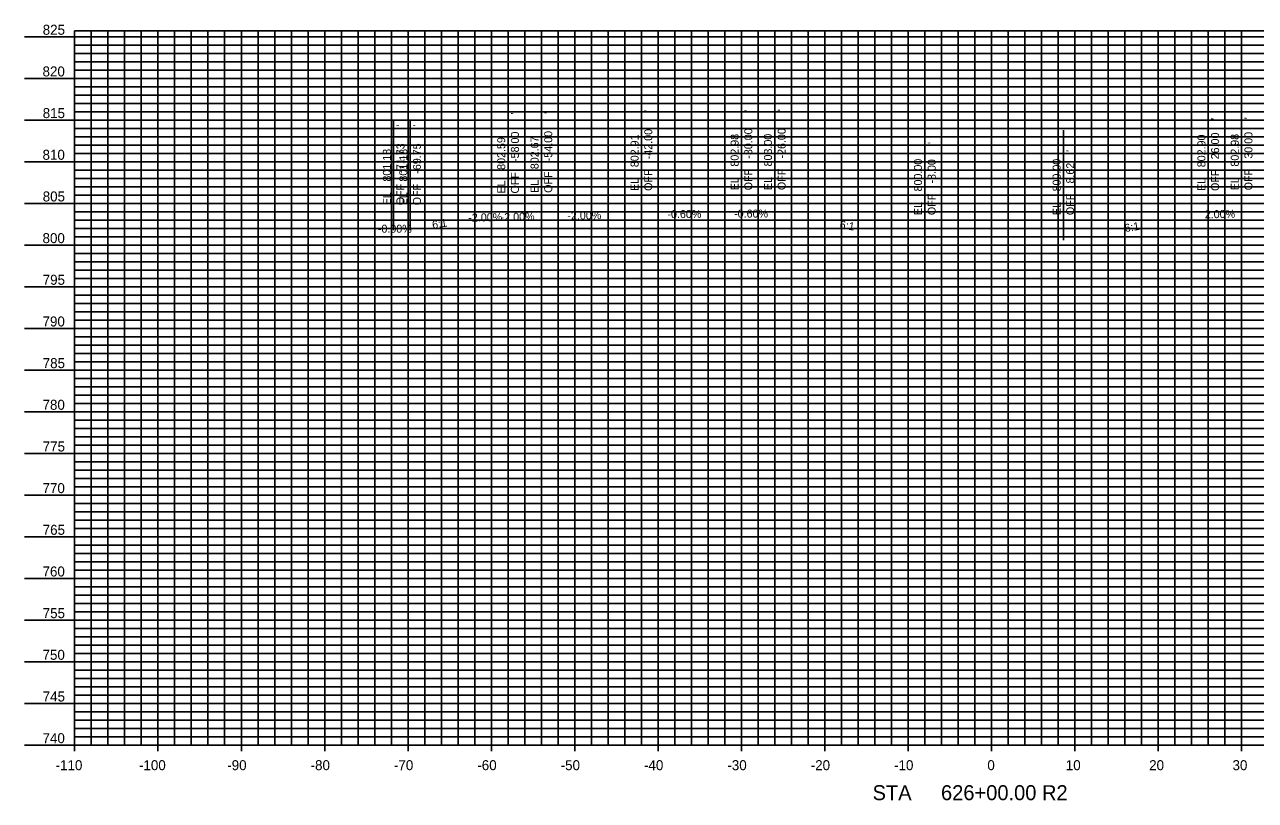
# Model space of a CAD drawing. Extents: x -116 to 176, y 733 to 826.
# Drawn here: x -116 to 31.7, y 733.4 to 826.5 of the extents above; entities that cross this region are included whole.
import ezdxf

# ---------------------------------------------------------------- set-up
doc = ezdxf.new("R2010")
doc.units = 0
for name, color, linetype in [('Default', 7, 'Continuous'), ('XS-Feature Text', 7, 'Continuous'), ('XS-Grid Lines', 7, 'Continuous'), ('XS-Segment Text', 7, 'Continuous'), ('XS-Sheet Major Grid Lines', 7, 'Continuous'), ('XS-Sheet Minor Grid Lines', 7, 'Continuous'), ('XS-Text', 7, 'Continuous')]:
    doc.layers.add(name, color=color, linetype=linetype)

msp = doc.modelspace()

# ---------------------------------------------------------------- linework, layer by layer
at = {"layer": 'XS-Feature Text'}
for p, q in [((-42, 803.51), (-42, 816.71)), ((-30, 803.58), (-30, 816.78)), ((-26, 803.6), (-26, 816.8)), ((26, 803.5), (26, 816.7)), ((30, 803.58), (30, 816.78)), ((-58, 803.19), (-58, 816.39)), ((-54, 803.27), (-54, 816.47)), ((-71.73, 801.78), (-71.73, 814.98)), ((-69.75, 801.78), (-69.75, 814.98)), ((-8, 800.6), (-8, 813.8)), ((8.62, 800.6), (8.62, 813.8))]:
    msp.add_line(p, q, dxfattribs=at)
at = {"layer": 'XS-Grid Lines'}
for p, q in [((-110, 825.71), (170, 825.71)), ((-110, 740), (-110, 825.71)), ((-110, 825), (-116, 825)), ((-110, 820), (-116, 820)), ((-110, 815), (-116, 815)), ((-110, 810), (-116, 810)), ((-110, 805), (-116, 805)), ((-110, 800), (-116, 800)), ((-110, 795), (-116, 795)), ((-110, 790), (-116, 790)), ((-110, 785), (-116, 785)), ((-110, 780), (-116, 780)), ((-110, 775), (-116, 775)), ((-110, 770), (-116, 770)), ((-110, 765), (-116, 765)), ((-110, 760), (-116, 760)), ((-110, 755), (-116, 755)), ((-110, 750), (-116, 750)), ((-110, 745), (-116, 745)), ((-110, 740), (-116, 740)), ((-110, 740), (170, 740)), ((-110, 740), (-110, 739.28)), ((-100, 740), (-100, 739.28)), ((-90, 740), (-90, 739.28)), ((-80, 740), (-80, 739.28)), ((-70, 740), (-70, 739.28)), ((-60, 740), (-60, 739.28)), ((-50, 740), (-50, 739.28)), ((-40, 740), (-40, 739.28)), ((-30, 740), (-30, 739.28)), ((-20, 740), (-20, 739.28)), ((-10, 740), (-10, 739.28)), ((0, 740), (0, 739.28)), ((10, 740), (10, 739.28)), ((20, 740), (20, 739.28)), ((30, 740), (30, 739.28))]:
    msp.add_line(p, q, dxfattribs=at)
at = {"layer": 'XS-Sheet Major Grid Lines'}
for p, q in [((-100, 740), (-100, 825.71)), ((-90, 740), (-90, 825.71)), ((-80, 740), (-80, 825.71)), ((-70, 740), (-70, 825.71)), ((-60, 740), (-60, 825.71)), ((-50, 740), (-50, 825.71)), ((-40, 740), (-40, 825.71)), ((-30, 740), (-30, 825.71)), ((-20, 740), (-20, 825.71)), ((-10, 740), (-10, 825.71)), ((0, 740), (0, 825.71)), ((10, 740), (10, 825.71)), ((20, 740), (20, 825.71)), ((30, 740), (30, 825.71)), ((-110, 825), (170, 825)), ((-110, 820), (170, 820)), ((-110, 815), (170, 815)), ((-110, 810), (170, 810)), ((-110, 805), (170, 805)), ((-110, 800), (170, 800)), ((-110, 795), (170, 795)), ((-110, 790), (170, 790)), ((-110, 785), (170, 785)), ((-110, 780), (170, 780)), ((-110, 775), (170, 775)), ((-110, 770), (170, 770)), ((-110, 765), (170, 765)), ((-110, 760), (170, 760)), ((-110, 755), (170, 755)), ((-110, 750), (170, 750)), ((-110, 745), (170, 745))]:
    msp.add_line(p, q, dxfattribs=at)
at = {"layer": 'XS-Sheet Minor Grid Lines'}
for p, q in [((-108, 740), (-108, 825.71)), ((-106, 740), (-106, 825.71)), ((-104, 740), (-104, 825.71)), ((-102, 740), (-102, 825.71)), ((-98, 740), (-98, 825.71)), ((-96, 740), (-96, 825.71)), ((-94, 740), (-94, 825.71)), ((-92, 740), (-92, 825.71)), ((-88, 740), (-88, 825.71)), ((-86, 740), (-86, 825.71)), ((-84, 740), (-84, 825.71)), ((-82, 740), (-82, 825.71)), ((-78, 740), (-78, 825.71)), ((-76, 740), (-76, 825.71)), ((-74, 740), (-74, 825.71)), ((-72, 740), (-72, 825.71)), ((-68, 740), (-68, 825.71)), ((-66, 740), (-66, 825.71)), ((-64, 740), (-64, 825.71)), ((-62, 740), (-62, 825.71)), ((-58, 740), (-58, 825.71)), ((-56, 740), (-56, 825.71)), ((-54, 740), (-54, 825.71)), ((-52, 740), (-52, 825.71)), ((-48, 740), (-48, 825.71)), ((-46, 740), (-46, 825.71)), ((-44, 740), (-44, 825.71)), ((-42, 740), (-42, 825.71)), ((-38, 740), (-38, 825.71)), ((-36, 740), (-36, 825.71)), ((-34, 740), (-34, 825.71)), ((-32, 740), (-32, 825.71)), ((-28, 740), (-28, 825.71)), ((-26, 740), (-26, 825.71)), ((-24, 740), (-24, 825.71)), ((-22, 740), (-22, 825.71)), ((-18, 740), (-18, 825.71)), ((-16, 740), (-16, 825.71)), ((-14, 740), (-14, 825.71)), ((-12, 740), (-12, 825.71)), ((-8, 740), (-8, 825.71)), ((-6, 740), (-6, 825.71)), ((-4, 740), (-4, 825.71)), ((-2, 740), (-2, 825.71)), ((2, 740), (2, 825.71)), ((4, 740), (4, 825.71)), ((6, 740), (6, 825.71)), ((8, 740), (8, 825.71)), ((12, 740), (12, 825.71)), ((14, 740), (14, 825.71)), ((16, 740), (16, 825.71)), ((18, 740), (18, 825.71)), ((22, 740), (22, 825.71)), ((24, 740), (24, 825.71)), ((26, 740), (26, 825.71)), ((28, 740), (28, 825.71)), ((-110, 824), (170, 824)), ((-110, 823), (170, 823)), ((-110, 822), (170, 822)), ((-110, 821), (170, 821)), ((-110, 819), (170, 819)), ((-110, 818), (170, 818)), ((-110, 817), (170, 817)), ((-110, 816), (170, 816)), ((-110, 814), (170, 814)), ((-110, 813), (170, 813)), ((-110, 812), (170, 812)), ((-110, 811), (170, 811)), ((-110, 809), (170, 809)), ((-110, 808), (170, 808)), ((-110, 807), (170, 807)), ((-110, 806), (170, 806)), ((-110, 804), (170, 804)), ((-110, 803), (170, 803)), ((-110, 802), (170, 802)), ((-110, 801), (170, 801)), ((-110, 799), (170, 799)), ((-110, 798), (170, 798)), ((-110, 797), (170, 797)), ((-110, 796), (170, 796)), ((-110, 794), (170, 794)), ((-110, 793), (170, 793)), ((-110, 792), (170, 792)), ((-110, 791), (170, 791)), ((-110, 789), (170, 789)), ((-110, 788), (170, 788)), ((-110, 787), (170, 787)), ((-110, 786), (170, 786)), ((-110, 784), (170, 784)), ((-110, 783), (170, 783)), ((-110, 782), (170, 782)), ((-110, 781), (170, 781)), ((-110, 779), (170, 779)), ((-110, 778), (170, 778)), ((-110, 777), (170, 777)), ((-110, 776), (170, 776)), ((-110, 774), (170, 774)), ((-110, 773), (170, 773)), ((-110, 772), (170, 772)), ((-110, 771), (170, 771)), ((-110, 769), (170, 769)), ((-110, 768), (170, 768)), ((-110, 767), (170, 767)), ((-110, 766), (170, 766)), ((-110, 764), (170, 764)), ((-110, 763), (170, 763)), ((-110, 762), (170, 762)), ((-110, 761), (170, 761)), ((-110, 759), (170, 759)), ((-110, 758), (170, 758)), ((-110, 757), (170, 757)), ((-110, 756), (170, 756)), ((-110, 754), (170, 754)), ((-110, 753), (170, 753)), ((-110, 752), (170, 752)), ((-110, 751), (170, 751)), ((-110, 749), (170, 749)), ((-110, 748), (170, 748)), ((-110, 747), (170, 747)), ((-110, 746), (170, 746)), ((-110, 744), (170, 744)), ((-110, 743), (170, 743)), ((-110, 742), (170, 742)), ((-110, 741), (170, 741))]:
    msp.add_line(p, q, dxfattribs=at)

# ---------------------------------------------------------------- texts
at = {"layer": 'Default'}
for s, p in [('825', (-113.83, 825.24)), ('820', (-113.85, 820.24)), ('815', (-113.83, 815.24)), ('810', (-113.85, 810.24)), ('805', (-113.83, 805.24)), ('800', (-113.85, 800.24)), ('795', (-113.83, 795.24)), ('790', (-113.85, 790.24)), ('785', (-113.83, 785.24)), ('780', (-113.85, 780.24)), ('775', (-113.83, 775.24)), ('770', (-113.85, 770.24)), ('765', (-113.83, 765.24)), ('760', (-113.85, 760.24)), ('755', (-113.83, 755.24)), ('750', (-113.85, 750.24)), ('745', (-113.83, 745.24)), ('740', (-113.85, 740.24))]:
    msp.add_text(s, height=1.2, dxfattribs=at).set_placement(p)
at = {"layer": 'XS-Feature Text'}
for s, p in [("'", (-56.7, 815.66)), ("'", (-52.7, 815.74)), ("'", (-40.7, 815.98)), ("'", (-28.7, 816.05)), ("'", (-24.7, 816.07)), ("'", (27.3, 815.02)), ("'", (31.3, 815.1)), ("'", (-70.43, 814.25)), ("'", (-68.45, 814.25)), ('-54.00', (-52.7, 810.06)), ('-42.00', (-40.7, 810.3)), ('-30.00', (-28.7, 810.37)), ('-26.00', (-24.7, 810.39)), ('-71.73', (-70.43, 808.57)), ('-69.75', (-68.45, 808.57)), ('802.59', (-58.34, 809.03)), ('-58.00', (-56.7, 809.98)), ('802.67', (-54.34, 809.11)), ('802.91', (-42.34, 809.35)), ('802.98', (-30.34, 809.42)), ('803.00', (-26.34, 809.44)), ("'", (-6.7, 812.13)), ('802.90', (25.66, 809.34)), ('26.00', (27.3, 810.29)), ('802.98', (29.66, 809.42)), ('30.00', (31.3, 810.37)), ('801.18', (-72.06, 807.62)), ('801.18', (-70.09, 807.62)), ("'", (9.92, 811.18)), ('800.00', (-8.34, 806.44)), ('-8.00', (-6.7, 807.39)), ('800.00', (8.29, 806.44)), ('8.62', (9.92, 807.39)), ('EL ', (-58.34, 806.19)), ('OFF ', (-56.7, 806.19)), ('EL ', (-54.34, 806.27)), ('OFF ', (-52.7, 806.27)), ('EL ', (-42.34, 806.51)), ('OFF ', (-40.7, 806.51)), ('EL ', (-30.34, 806.58)), ('OFF ', (-28.7, 806.58)), ('EL ', (-26.34, 806.6)), ('OFF ', (-24.7, 806.6)), ('EL ', (25.66, 806.5)), ('OFF ', (27.3, 806.5)), ('EL ', (29.66, 806.58)), ('OFF ', (31.3, 806.58)), ('EL ', (-72.06, 804.78)), ('OFF ', (-70.43, 804.78)), ('EL ', (-70.09, 804.78)), ('OFF ', (-68.45, 804.78)), ('EL ', (-8.34, 803.6)), ('OFF ', (-6.7, 803.6)), ('EL ', (8.29, 803.6)), ('OFF ', (9.92, 803.6))]:
    msp.add_text(s, height=0.96, rotation=90, dxfattribs=at).set_placement(p)
at = {"layer": 'XS-Segment Text'}
for s, rotation, p in [('-2.00%', 1.1458, (-62.76, 802.81)), ('-2.00%', 1.1458, (-58.88, 802.88)), ('-2.00%', 1.1458, (-50.88, 803.04)), ('-0.60%', 0.3429, (-38.88, 803.24)), ('-0.60%', 0.3429, (-30.88, 803.29)), ('2.00%', 1.1458, (25.59, 803.21)), ('6:1', 9.4625, (-67.03, 801.95)), ('6:1', 350.5377, (-18.27, 802.03)), ('6:1', 9.4623, (16.04, 801.55))]:
    msp.add_text(s, height=0.96, rotation=rotation, dxfattribs=at).set_placement(p)
msp.add_text('-0.00%', height=0.96, dxfattribs=at).set_placement((-73.62, 801.49))
at = {"layer": 'XS-Text'}
for s, height, p in [('-110', 1.2, (-112.28, 737)), ('-100', 1.2, (-102.28, 737)), ('-90', 1.2, (-91.69, 737)), ('-80', 1.2, (-81.69, 737)), ('-70', 1.2, (-71.69, 737)), ('-60', 1.2, (-61.69, 737)), ('-50', 1.2, (-51.69, 737)), ('-40', 1.2, (-41.69, 737)), ('-30', 1.2, (-31.69, 737)), ('-20', 1.2, (-21.69, 737)), ('-10', 1.2, (-11.69, 737)), ('0', 1.2, (-0.5, 737)), ('10', 1.2, (8.91, 737)), ('20', 1.2, (18.91, 737)), ('30', 1.2, (28.91, 737)), (' STA ', 1.8, (-14.94, 733.4)), ('626+00.00 R2', 1.8, (-6.06, 733.4))]:
    msp.add_text(s, height=height, dxfattribs=at).set_placement(p)

doc.saveas('drawing.dxf')
